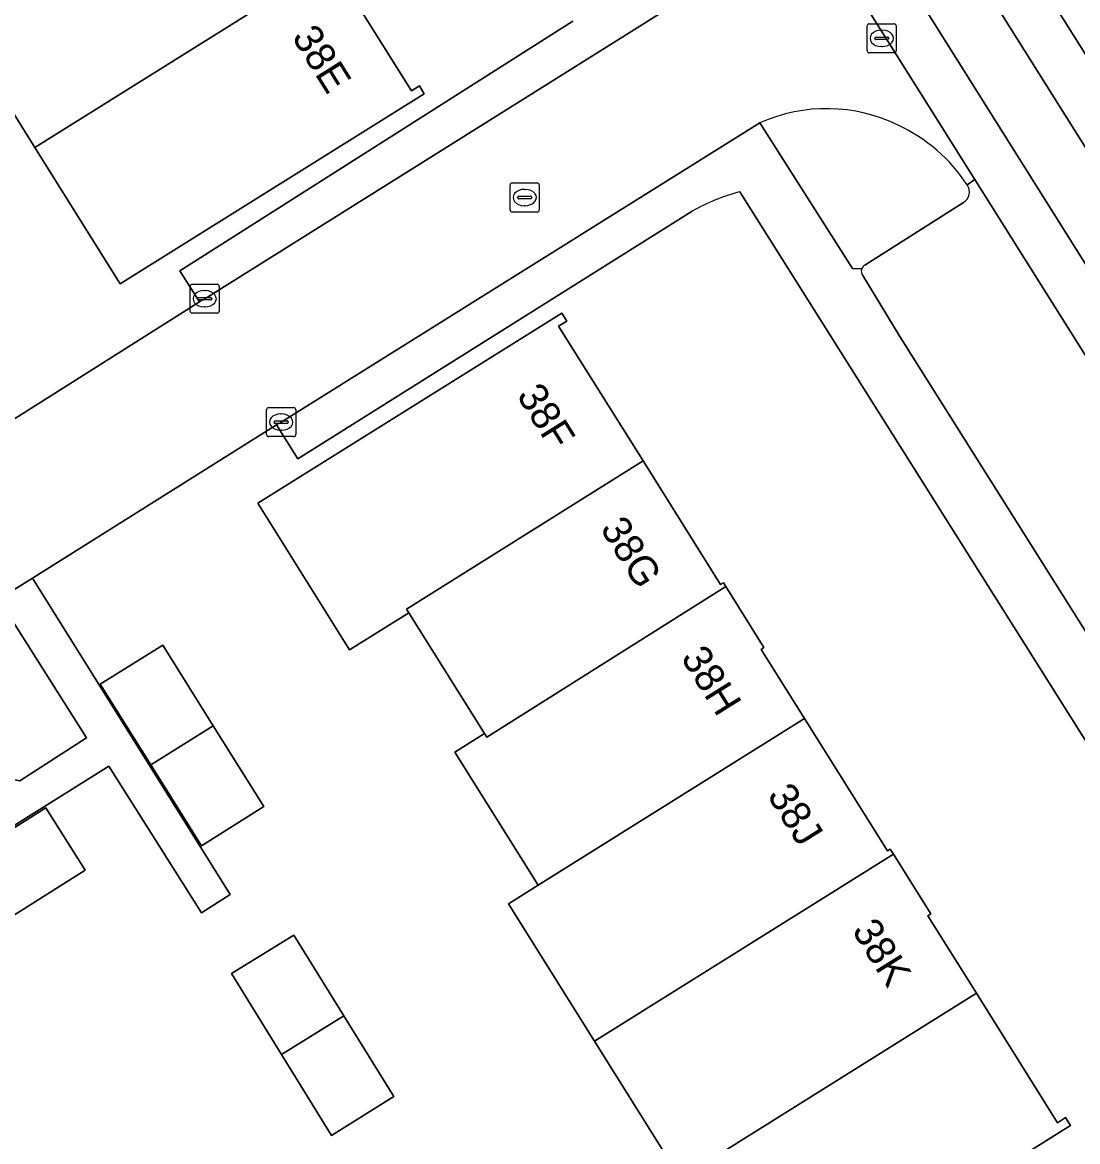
# Model space of a CAD drawing. Extents: x 160077 to 160948, y 386481 to 387498.
# Drawn here: x 160452.92 to 160489.16, y 386932.94 to 386971.39 of the extents above; entities that cross this region are included whole.
import ezdxf

# ---------------------------------------------------------------- set-up
doc = ezdxf.new("R2010")
doc.units = 0
for name, color, linetype in [('IMGEO_Erf', 7, 'Continuous'), ('IMGEO_Groenvoorziening', 7, 'Continuous'), ('IMGEO_Kolk', 7, 'Continuous'), ('IMGEO_Pand', 7, 'Continuous'), ('IMGEO_Pand_nummerreeks', 7, 'Continuous'), ('IMGEO_Parkeervlak_open', 7, 'Continuous'), ('IMGEO_Rijbaan_lokaal_gesloten', 7, 'Continuous'), ('IMGEO_Rijbaan_lokaal_open', 7, 'Continuous'), ('IMGEO_Rioolput', 7, 'Continuous'), ('IMGEO_Voetpad_open', 7, 'Continuous')]:
    doc.layers.add(name, color=color, linetype=linetype)

msp = doc.modelspace()

# ---------------------------------------------------------------- linework, layer by layer
at = {"layer": 'IMGEO_Erf'}
for points in [[(160452.03, 386991.789), (160453.593, 386989.288), (160453.691, 386989.35), (160454.902, 386987.411), (160455.088, 386987.114), (160454.992, 386987.054), (160457.639, 386982.831), (160459.331, 386980.131), (160459.428, 386980.192), (160460.67, 386978.203), (160460.819, 386977.964), (160460.722, 386977.904), (160463.511, 386973.456), (160466.279, 386969.039), (160466.55, 386969.209), (160466.72, 386968.936), (160456.277, 386962.403), (160453.342, 386967.092), (160450.408, 386971.781)], [(160458.325, 386962.854), (160471.824, 386971.434)], [(160475.918, 386964.905), (160462.379, 386956.397), (160461.648, 386957.56), (160453.259, 386952.3), (160460.053, 386941.437), (160459.063, 386940.798), (160455.889, 386945.843), (160435.694, 386933.19), (160432.21, 386938.761), (160432.328, 386938.842), (160432.243, 386938.981), (160429.497, 386943.42), (160429.429, 386943.531), (160429.299, 386943.448), (160425.736, 386949.039), (160445.881, 386961.646), (160442.698, 386966.723), (160443.7, 386967.364), (160450.547, 386956.452), (160459.004, 386961.786), (160458.325, 386962.854)], [(160495.506, 386937.067), (160477.559, 386965.572)], [(160475.521, 386931.675), (160472.568, 386936.393), (160469.614, 386941.11), (160470.635, 386941.75), (160467.768, 386946.326), (160468.787, 386946.964), (160466.189, 386951.111), (160464.15, 386949.834), (160460.998, 386954.868), (160471.438, 386961.4), (160471.609, 386961.126), (160471.331, 386960.951), (160474.233, 386956.326), (160476.896, 386952.08), (160476.991, 386952.139), (160477.07, 386952.013), (160478.384, 386949.915), (160478.282, 386949.851), (160479.771, 386947.477), (160482.622, 386942.929), (160482.722, 386942.991), (160482.83, 386942.818), (160484.109, 386940.763), (160484.015, 386940.704), (160485.682, 386938.037), (160488.46, 386933.591), (160488.741, 386933.767), (160488.911, 386933.495), (160478.475, 386926.958)]]:
    msp.add_lwpolyline(points, dxfattribs=at)
for points in [[(160457.734, 386949.999), (160459.47, 386947.225), (160461.205, 386944.451), (160459.062, 386943.107), (160457.324, 386945.883), (160455.587, 386948.657)], [(160453.722, 386944.405), (160455.069, 386942.264), (160452.297, 386940.518), (160449.531, 386938.777), (160448.178, 386940.934), (160450.95, 386942.67)], [(160462.234, 386940.04), (160463.956, 386937.268), (160465.678, 386934.496), (160463.536, 386933.154), (160461.815, 386935.938), (160460.097, 386938.715)]]:
    msp.add_lwpolyline(points, close=True, dxfattribs=at)
msp.add_arc((160479.493, 386958.463), 7.367, 105.2151, 119.0244, dxfattribs=at)
at = {"layer": 'IMGEO_Groenvoorziening'}
for points in [[(160478.244, 386967.936), (160481.428, 386962.931), (160481.741, 386962.923)], [(160481.851, 386963.052), (160485.236, 386965.2)], [(160452.484, 386945.4), (160452.823, 386945.335), (160455.12, 386946.808), (160452.098, 386951.572)]]:
    msp.add_lwpolyline(points, dxfattribs=at)
for centre, radius, start, end in [((160480.531, 386962.821), 5.603, 63.9086, 114.0897), ((160480.6, 386962.683), 5.698, 33.2484, 65.144), ((160485.022, 386965.563), 0.421, 300.5187, 35.4852), ((160481.979, 386962.832), 0.254, 120.0864, 159.0043)]:
    msp.add_arc(centre, radius, start, end, dxfattribs=at)
at = {"layer": 'IMGEO_Kolk'}
for p, q in [((160481.927, 386970.414), (160481.927, 386971.266)), ((160482.002, 386971.34), (160482.854, 386971.34)), ((160482.415, 386971.12), (160482.44, 386971.12)), ((160482.928, 386971.266), (160482.928, 386970.414)), ((160482.186, 386970.834), (160482.186, 386970.846)), ((160482.624, 386970.797), (160482.226, 386970.797)), ((160482.229, 386970.883), (160482.627, 386970.883)), ((160482.67, 386970.846), (160482.67, 386970.834)), ((160482.854, 386970.34), (160482.002, 386970.34)), ((160482.438, 386970.56), (160482.413, 386970.56)), ((160458.676, 386961.469), (160458.676, 386962.321)), ((160458.751, 386962.395), (160459.603, 386962.395)), ((160459.677, 386962.321), (160459.677, 386961.469)), ((160458.935, 386961.889), (160458.935, 386961.901)), ((160458.978, 386961.938), (160459.376, 386961.938)), ((160459.164, 386962.175), (160459.189, 386962.175)), ((160459.419, 386961.901), (160459.419, 386961.889)), ((160459.373, 386961.852), (160458.975, 386961.852)), ((160459.187, 386961.615), (160459.162, 386961.615)), ((160459.603, 386961.395), (160458.751, 386961.395)), ((160461.304, 386957.232), (160461.304, 386958.084)), ((160461.379, 386958.158), (160462.231, 386958.158)), ((160462.305, 386958.084), (160462.305, 386957.232)), ((160461.563, 386957.652), (160461.563, 386957.664)), ((160461.606, 386957.701), (160462.004, 386957.701)), ((160461.792, 386957.938), (160461.817, 386957.938)), ((160462.047, 386957.664), (160462.047, 386957.652)), ((160462.001, 386957.615), (160461.603, 386957.615)), ((160461.815, 386957.378), (160461.79, 386957.378)), ((160462.231, 386957.158), (160461.379, 386957.158))]:
    msp.add_line(p, q, dxfattribs=at)
for points in [[(160481.927, 386970.414), (160481.927, 386971.266)], [(160482.002, 386971.34), (160482.854, 386971.34)], [(160482.928, 386971.266), (160482.928, 386970.414)], [(160482.854, 386970.34), (160482.002, 386970.34)], [(160458.676, 386961.469), (160458.676, 386962.321)], [(160458.751, 386962.395), (160459.603, 386962.395)], [(160459.677, 386962.321), (160459.677, 386961.469)], [(160459.603, 386961.395), (160458.751, 386961.395)], [(160461.304, 386957.232), (160461.304, 386958.084)], [(160461.379, 386958.158), (160462.231, 386958.158)], [(160462.305, 386958.084), (160462.305, 386957.232)], [(160462.231, 386957.158), (160461.379, 386957.158)]]:
    msp.add_lwpolyline(points, dxfattribs=at)
for centre, radius, start, end in [((160482.004, 386971.264), 0.0765, 91.552, 178.448), ((160482.004, 386971.264), 0.0765, 91.552, 178.448), ((160482.852, 386971.264), 0.0765, 1.552, 88.448), ((160482.852, 386971.264), 0.0765, 1.552, 88.448), ((160482.226, 386970.843), 0.0403, 85.8775, 175.7526), ((160482.223, 386970.833), 0.0366, 178.938, 274.7102), ((160482.627, 386970.84), 0.043, 264.8664, 352.4533), ((160482.631, 386970.845), 0.0386, 1.7309, 96.639), ((160482.004, 386970.416), 0.0765, 181.552, 268.448), ((160482.004, 386970.416), 0.0765, 181.552, 268.448), ((160482.852, 386970.416), 0.0765, 271.552, 358.448), ((160482.852, 386970.416), 0.0765, 271.552, 358.448), ((160458.753, 386962.319), 0.0765, 91.552, 178.448), ((160458.753, 386962.319), 0.0765, 91.552, 178.448), ((160459.601, 386962.319), 0.0765, 1.552, 88.448), ((160459.601, 386962.319), 0.0765, 1.552, 88.448), ((160458.975, 386961.898), 0.0403, 85.8775, 175.7526), ((160458.972, 386961.888), 0.0366, 178.938, 274.7102), ((160459.376, 386961.895), 0.043, 264.8664, 352.4533), ((160459.38, 386961.9), 0.0386, 1.7309, 96.639), ((160458.753, 386961.471), 0.0765, 181.552, 268.448), ((160458.753, 386961.471), 0.0765, 181.552, 268.448), ((160459.601, 386961.471), 0.0765, 271.552, 358.448), ((160459.601, 386961.471), 0.0765, 271.552, 358.448), ((160461.381, 386958.082), 0.0765, 91.552, 178.448), ((160461.381, 386958.082), 0.0765, 91.552, 178.448), ((160462.229, 386958.082), 0.0765, 1.552, 88.448), ((160462.229, 386958.082), 0.0765, 1.552, 88.448), ((160461.603, 386957.661), 0.0403, 85.8775, 175.7526), ((160461.6, 386957.651), 0.0366, 178.938, 274.7102), ((160462.004, 386957.658), 0.043, 264.8664, 352.4533), ((160462.008, 386957.663), 0.0386, 1.7309, 96.639), ((160461.381, 386957.234), 0.0765, 181.552, 268.448), ((160461.381, 386957.234), 0.0765, 181.552, 268.448), ((160462.229, 386957.234), 0.0765, 271.552, 358.448), ((160462.229, 386957.234), 0.0765, 271.552, 358.448)]:
    msp.add_arc(centre, radius, start, end, dxfattribs=at)
for centre, major_axis, ratio, start_param, end_param in [((160482.414, 386970.84), (-0.387, 0.002), 0.722429, 4.712389, 7.853982), ((160482.439, 386970.84), (-0.39, 0.002), 0.717154, 1.570796, 4.712389), ((160459.163, 386961.895), (-0.387, 0.002), 0.722429, 4.712389, 7.853982), ((160459.188, 386961.895), (-0.39, 0.002), 0.717154, 1.570796, 4.712389), ((160461.791, 386957.658), (-0.387, 0.002), 0.722429, 4.712389, 7.853982), ((160461.816, 386957.658), (-0.39, 0.002), 0.717154, 1.570796, 4.712389)]:
    msp.add_ellipse(centre, major_axis=major_axis, ratio=ratio, start_param=start_param, end_param=end_param, dxfattribs=at)
at = {"layer": 'IMGEO_Pand'}
for points in [[(160463.511, 386973.456), (160460.722, 386977.904), (160460.819, 386977.964), (160460.67, 386978.203), (160450.408, 386971.781), (160453.342, 386967.092)], [(160466.72, 386968.936), (160466.55, 386969.209), (160466.279, 386969.039), (160463.511, 386973.456), (160453.342, 386967.092), (160456.277, 386962.403)], [(160474.233, 386956.326), (160471.331, 386960.951), (160471.609, 386961.126), (160471.438, 386961.4), (160460.998, 386954.868), (160464.15, 386949.834), (160466.189, 386951.111), (160466.109, 386951.238)], [(160477.07, 386952.013), (160476.991, 386952.139), (160476.896, 386952.08), (160474.233, 386956.326), (160466.109, 386951.238), (160466.189, 386951.111), (160468.787, 386946.964), (160468.865, 386946.84)], [(160479.771, 386947.477), (160478.282, 386949.851), (160478.384, 386949.915), (160477.07, 386952.013), (160468.865, 386946.84), (160468.787, 386946.964), (160467.768, 386946.326), (160470.635, 386941.75)], [(160457.734, 386949.999), (160455.587, 386948.657), (160457.324, 386945.883), (160459.47, 386947.225)], [(160482.83, 386942.818), (160482.722, 386942.991), (160482.622, 386942.929), (160479.771, 386947.477), (160470.635, 386941.75), (160469.614, 386941.11), (160472.568, 386936.393)], [(160459.47, 386947.225), (160457.324, 386945.883), (160459.062, 386943.107), (160461.205, 386944.451)], [(160453.722, 386944.405), (160450.95, 386942.67), (160452.297, 386940.518), (160455.069, 386942.264)], [(160485.682, 386938.037), (160484.015, 386940.704), (160484.109, 386940.763), (160482.83, 386942.818), (160472.568, 386936.393), (160475.521, 386931.675)], [(160462.234, 386940.04), (160460.097, 386938.715), (160461.815, 386935.938), (160463.956, 386937.268)], [(160488.911, 386933.495), (160488.741, 386933.767), (160488.46, 386933.591), (160485.682, 386938.037), (160475.521, 386931.675), (160478.475, 386926.958)], [(160463.956, 386937.268), (160461.815, 386935.938), (160463.536, 386933.154), (160465.678, 386934.496)]]:
    msp.add_lwpolyline(points, close=True, dxfattribs=at)
at = {"layer": 'IMGEO_Parkeervlak_open'}
for points in [[(160485.624, 386965.994), (160485.365, 386965.807)], [(160495.448, 386950.36), (160485.624, 386965.994)], [(160485.236, 386965.2), (160481.851, 386963.052)], [(160481.776, 386962.688), (160483.047, 386960.595), (160490.82, 386948.26)]]:
    msp.add_lwpolyline(points, dxfattribs=at)
for centre, radius, start, end in [((160485.022, 386965.563), 0.421, 300.5187, 35.4852), ((160481.979, 386962.832), 0.254, 120.0864, 159.0043), ((160481.97, 386962.837), 0.244, 159.3741, 217.5682)]:
    msp.add_arc(centre, radius, start, end, dxfattribs=at)
at = {"layer": 'IMGEO_Rijbaan_lokaal_gesloten'}
for points in [[(160466.642, 387006.564), (160465.2, 387005.644), (160503.723, 386944.337), (160505.157, 386945.256), (160504.006, 386947.109), (160495.253, 386961.028), (160486.501, 386974.953), (160477.229, 386989.731), (160467.421, 387005.35)], [(160463.407, 387004.517), (160461.998, 387003.612), (160462.653, 387002.551), (160465.979, 386997.266), (160469.534, 386991.602), (160476.969, 386979.769), (160485.624, 386965.994), (160495.448, 386950.36), (160499.853, 386943.394), (160500.523, 386942.324), (160501.896, 386943.239)]]:
    msp.add_lwpolyline(points, close=True, dxfattribs=at)
at = {"layer": 'IMGEO_Rijbaan_lokaal_open'}
msp.add_lwpolyline([(160465.2, 387005.644), (160463.407, 387004.517), (160501.896, 386943.239), (160503.723, 386944.337)], close=True, dxfattribs=at)
for points in [[(160485.365, 386965.807), (160485.624, 386965.994), (160476.969, 386979.769), (160476.72, 386979.602)], [(160475.566, 386972.176), (160459.177, 386961.895), (160459.004, 386961.786), (160450.547, 386956.452), (160449.418, 386955.74), (160447.395, 386954.464)], [(160461.648, 386957.56), (160461.805, 386957.658), (160478.244, 386967.936)], [(160450.044, 386950.284), (160452.098, 386951.572), (160453.259, 386952.3), (160461.648, 386957.56)]]:
    msp.add_lwpolyline(points, dxfattribs=at)
for centre, radius, start, end in [((160480.531, 386962.821), 5.603, 63.9086, 114.0897), ((160480.6, 386962.683), 5.698, 33.2484, 65.144)]:
    msp.add_arc(centre, radius, start, end, dxfattribs=at)
at = {"layer": 'IMGEO_Rioolput'}
for p, q in [((160469.666, 386964.945), (160469.666, 386965.797)), ((160469.741, 386965.871), (160470.593, 386965.871)), ((160470.667, 386965.797), (160470.667, 386964.945)), ((160469.925, 386965.365), (160469.925, 386965.377)), ((160469.968, 386965.414), (160470.366, 386965.414)), ((160470.154, 386965.651), (160470.179, 386965.651)), ((160470.409, 386965.377), (160470.409, 386965.365)), ((160470.363, 386965.328), (160469.965, 386965.328)), ((160470.177, 386965.091), (160470.152, 386965.091)), ((160470.593, 386964.871), (160469.741, 386964.871))]:
    msp.add_line(p, q, dxfattribs=at)
for points in [[(160469.666, 386964.945), (160469.666, 386965.797)], [(160469.741, 386965.871), (160470.593, 386965.871)], [(160470.667, 386965.797), (160470.667, 386964.945)], [(160470.593, 386964.871), (160469.741, 386964.871)]]:
    msp.add_lwpolyline(points, dxfattribs=at)
for centre, radius, start, end in [((160469.743, 386965.795), 0.0765, 91.552, 178.448), ((160469.743, 386965.795), 0.0765, 91.552, 178.448), ((160470.591, 386965.795), 0.0765, 1.552, 88.448), ((160470.591, 386965.795), 0.0765, 1.552, 88.448), ((160469.965, 386965.374), 0.0403, 85.8775, 175.7526), ((160469.962, 386965.364), 0.0366, 178.938, 274.7102), ((160470.366, 386965.371), 0.043, 264.8664, 352.4533), ((160470.37, 386965.376), 0.0386, 1.7309, 96.639), ((160469.743, 386964.947), 0.0765, 181.552, 268.448), ((160469.743, 386964.947), 0.0765, 181.552, 268.448), ((160470.591, 386964.947), 0.0765, 271.552, 358.448), ((160470.591, 386964.947), 0.0765, 271.552, 358.448)]:
    msp.add_arc(centre, radius, start, end, dxfattribs=at)
for centre, major_axis, ratio, start_param, end_param in [((160470.153, 386965.371), (-0.387, 0.002), 0.722429, 4.712389, 7.853982), ((160470.178, 386965.371), (-0.39, 0.002), 0.717154, 1.570796, 4.712389)]:
    msp.add_ellipse(centre, major_axis=major_axis, ratio=ratio, start_param=start_param, end_param=end_param, dxfattribs=at)
at = {"layer": 'IMGEO_Voetpad_open'}
for points in [[(160456.003, 387023.539), (160466.121, 387007.413), (160466.642, 387006.564), (160467.421, 387005.35), (160477.229, 386989.731), (160486.501, 386974.953), (160495.253, 386961.028), (160504.006, 386947.109), (160505.157, 386945.256), (160505.706, 386944.383), (160516.604, 386927.056), (160517.146, 386926.21), (160519.36, 386922.638), (160529.177, 386907.013), (160537.92, 386893.052), (160539.088, 386891.188), (160539.631, 386890.344), (160545.529, 386880.983)], [(160471.824, 386971.434), (160458.325, 386962.854), (160459.004, 386961.786), (160459.177, 386961.895), (160475.566, 386972.176), (160472.396, 386977.213), (160472.48, 386977.566)], [(160481.741, 386962.923), (160481.428, 386962.931), (160478.244, 386967.936), (160461.805, 386957.658), (160461.648, 386957.56), (160462.379, 386956.397), (160475.918, 386964.905)], [(160477.559, 386965.572), (160495.506, 386937.067)], [(160490.82, 386948.26), (160483.047, 386960.595), (160481.776, 386962.688)], [(160432.5, 386939.145), (160432.243, 386938.981), (160432.328, 386938.842), (160432.21, 386938.761), (160435.694, 386933.19), (160455.889, 386945.843), (160459.063, 386940.798), (160460.053, 386941.437), (160453.259, 386952.3)], [(160453.259, 386952.3), (160452.098, 386951.572), (160455.12, 386946.808), (160452.823, 386945.335), (160452.484, 386945.4)]]:
    msp.add_lwpolyline(points, dxfattribs=at)
for centre, radius, start, end in [((160479.493, 386958.463), 7.367, 105.2151, 119.0244), ((160481.97, 386962.837), 0.244, 159.3741, 217.5682)]:
    msp.add_arc(centre, radius, start, end, dxfattribs=at)

# ---------------------------------------------------------------- texts
at = {"layer": 'IMGEO_Pand_nummerreeks'}
for s, rotation, p in [('38E', 302.1026, (160462.149, 386970.884)), ('38F', 302.1026, (160469.872, 386958.573)), ('38G', 302.1026, (160472.739, 386954.003)), ('38H', 302.0854, (160475.509, 386949.566)), ('38J', 302.0854, (160478.474, 386944.838)), ('38K', 301.9995, (160481.385, 386940.196))]:
    msp.add_text(s, height=1, rotation=rotation, dxfattribs=at).set_placement(p)

doc.saveas('drawing.dxf')
